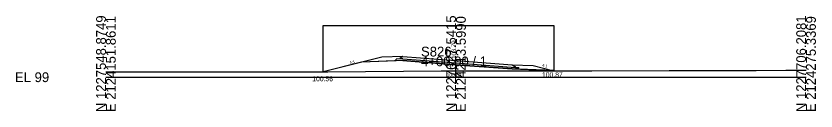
# Model space of a CAD drawing. Extents: x 2118382 to 2118616, y 1213030 to 1222057.
# Drawn here: x 2118381.9 to 2118610.4, y 1214530.1 to 1214557.3 of the extents above; entities that cross this region are included whole.
import ezdxf

# ---------------------------------------------------------------- set-up
doc = ezdxf.new("R2010")
doc.units = 0
for name, color, linetype in [('XS_CELL', 7, 'Continuous'), ('XS_M_DITCH', 7, 'Continuous'), ('XS_M_SHAPES_EARTHWORK', 7, 'Continuous'), ('XS_P_FINISHED_GRADE', 7, 'Continuous'), ('XS_P_FINISHED_GRADE_ELEV_TX', 7, 'Continuous'), ('XS_P_SUBGRADE_GRANULAR', 7, 'Continuous'), ('XS_P_SUBGRADE_PAVEMENT', 7, 'Continuous'), ('XS_P_TX_DCH', 7, 'Continuous'), ('XS_P_TX_FS_BS', 7, 'Continuous'), ('XS_X_GROUND', 7, 'Continuous'), ('XS_X_GROUND_TX', 7, 'Continuous')]:
    doc.layers.add(name, color=color, linetype=linetype)

msp = doc.modelspace()

# ---------------------------------------------------------------- linework, layer by layer
at = {"layer": 'XS_CELL'}
for p, q in [((2118507.6, 1214539.8), (2118507.6, 1214545.73)), ((2118407.6, 1214539.8), (2118507.6, 1214539.8)), ((2118507.6, 1214539.8), (2118607.6, 1214539.8))]:
    msp.add_line(p, q, dxfattribs=at)
at = {"layer": 'XS_M_DITCH'}
for p, q in [((2118469.7, 1214541.36), (2118469.7, 1214554.59)), ((2118469.7, 1214554.59), (2118535.54, 1214554.59)), ((2118535.54, 1214554.59), (2118535.54, 1214541.67))]:
    msp.add_line(p, q, dxfattribs=at)
at = {"layer": 'XS_M_SHAPES_EARTHWORK'}
for p, q in [((2118480.6, 1214544.09), (2118469.7, 1214541.36)), ((2118507.6, 1214543.38), (2118492.37, 1214544.56)), ((2118523.69, 1214542.16), (2118507.6, 1214543.38)), ((2118469.7, 1214541.36), (2118469.99, 1214541.36)), ((2118469.99, 1214541.36), (2118470.58, 1214541.36)), ((2118470.58, 1214541.36), (2118470.95, 1214541.37)), ((2118470.95, 1214541.37), (2118503.37, 1214541.63)), ((2118503.37, 1214541.63), (2118507.6, 1214541.63)), ((2118507.6, 1214541.63), (2118535.54, 1214541.67)), ((2118535.54, 1214541.67), (2118535.46, 1214541.69))]:
    msp.add_line(p, q, dxfattribs=at)
for points in [[(2118492.37, 1214544.56), (2118490.53, 1214544.49), (2118480.6, 1214544.09)], [(2118535.46, 1214541.69), (2118525.54, 1214542.08), (2118523.69, 1214542.16)]]:
    msp.add_lwpolyline(points, dxfattribs=at)
at = {"layer": 'XS_P_FINISHED_GRADE'}
for p, q in [((2118492.37, 1214545.77), (2118486.37, 1214545.53)), ((2118492.37, 1214545.77), (2118507.6, 1214544.59)), ((2118486.37, 1214545.53), (2118469.7, 1214541.36)), ((2118507.6, 1214544.59), (2118523.69, 1214543.37)), ((2118523.69, 1214543.37), (2118529.69, 1214543.13)), ((2118529.69, 1214543.13), (2118535.54, 1214541.67))]:
    msp.add_line(p, q, dxfattribs=at)
at = {"layer": 'XS_P_SUBGRADE_GRANULAR'}
for p, q in [((2118492.37, 1214544.56), (2118480.6, 1214544.09)), ((2118491.53, 1214545.03), (2118490.53, 1214544.99)), ((2118490.53, 1214544.49), (2118490.53, 1214544.99)), ((2118492.37, 1214544.56), (2118507.6, 1214543.38)), ((2118507.6, 1214543.38), (2118523.69, 1214542.16)), ((2118523.69, 1214542.16), (2118535.46, 1214541.69)), ((2118524.56, 1214542.59), (2118525.54, 1214542.56)), ((2118525.54, 1214542.08), (2118525.54, 1214542.56))]:
    msp.add_line(p, q, dxfattribs=at)
at = {"layer": 'XS_P_SUBGRADE_PAVEMENT'}
for p, q in [((2118492.37, 1214545.77), (2118491.68, 1214545.29)), ((2118491.68, 1214545.29), (2118491.53, 1214545.03)), ((2118492.37, 1214545.06), (2118491.53, 1214545.03)), ((2118492.37, 1214545.06), (2118507.6, 1214543.88)), ((2118507.6, 1214543.88), (2118524.56, 1214542.59)), ((2118523.69, 1214543.37), (2118524.39, 1214542.88)), ((2118524.39, 1214542.88), (2118524.56, 1214542.59))]:
    msp.add_line(p, q, dxfattribs=at)
at = {"layer": 'XS_X_GROUND'}
for p, q in [((2118407.6, 1214541.3), (2118419.2, 1214541.32)), ((2118419.2, 1214541.32), (2118424.22, 1214541.3)), ((2118424.22, 1214541.3), (2118469.53, 1214541.37)), ((2118469.53, 1214541.37), (2118469.99, 1214541.36)), ((2118469.99, 1214541.36), (2118470.58, 1214541.36)), ((2118470.58, 1214541.36), (2118470.95, 1214541.37)), ((2118470.95, 1214541.37), (2118503.37, 1214541.63)), ((2118503.37, 1214541.63), (2118507.6, 1214541.63)), ((2118507.6, 1214541.63), (2118536.62, 1214541.67)), ((2118536.62, 1214541.67), (2118546.38, 1214541.64)), ((2118546.38, 1214541.64), (2118568.45, 1214541.74)), ((2118568.45, 1214541.74), (2118593.31, 1214541.75)), ((2118593.31, 1214541.75), (2118601.84, 1214541.77)), ((2118601.84, 1214541.77), (2118607.6, 1214541.78))]:
    msp.add_line(p, q, dxfattribs=at)

# ---------------------------------------------------------------- texts
at = {"layer": 'XS_CELL'}
for s, p in [('N 1227548.8749', (2118407.6, 1214529.8)), ('E 2124151.8611', (2118410.4, 1214529.8)), ('N 1227627.5415', (2118507.6, 1214529.8)), ('E 2124213.5990', (2118510.4, 1214529.8)), ('N 1227706.2081', (2118607.6, 1214529.8)), ('E 2124275.3369', (2118610.4, 1214529.8))]:
    msp.add_text(s, height=2.8, rotation=90, dxfattribs=at).set_placement(p)
for s, p in [('S826', (2118497.6, 1214545.73)), ('4+00.00 / 1', (2118497.6, 1214542.93)), ('EL 99', (2118381.6, 1214538.4))]:
    msp.add_text(s, height=2.8, dxfattribs=at).set_placement(p)
at = {"layer": 'XS_P_FINISHED_GRADE_ELEV_TX'}
msp.add_text(' 103.79', height=1.25, rotation=90, dxfattribs=at).set_placement((2118507.6, 1214544.57))
at = {"layer": 'XS_P_TX_DCH'}
for s, p in [('100.87', (2118532.18, 1214539.82)), ('100.56', (2118466.54, 1214538.64))]:
    msp.add_text(s, height=1.4, dxfattribs=at).set_placement(p)
at = {"layer": 'XS_P_TX_FS_BS'}
for rotation, p in [(14.0362, (2118477.33, 1214543.53)), (14.0362, (2118477.33, 1214543.53)), (345.9638, (2118532.14, 1214542.89))]:
    msp.add_text('4:1', height=0.8, rotation=rotation, dxfattribs=at).set_placement(p)
at = {"layer": 'XS_X_GROUND_TX'}
msp.add_text('100.83', height=1, dxfattribs=at).set_placement((2118504.95, 1214539.94))

doc.saveas('drawing.dxf')
